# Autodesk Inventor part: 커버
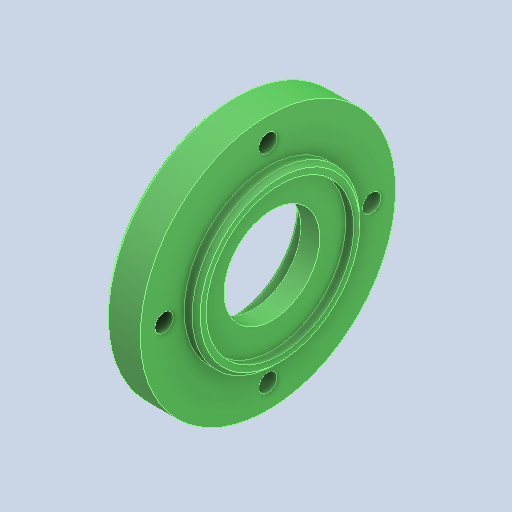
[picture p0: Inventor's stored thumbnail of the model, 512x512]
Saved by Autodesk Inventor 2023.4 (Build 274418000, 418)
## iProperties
Created: 2024-04
Part Number: 커버
Material: 알루미늄 6061
Document SubType Name: Modeling
Designer: EDU
Density: 2.71 g/cm^3
Appearance: 기본값
Author: jhkim
Sending System: Autodesk Inventor 2025
Preprocessor: ST-DEVELOPER v20
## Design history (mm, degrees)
node "커버1"
node "솔리드2"
node "솔리드1"
